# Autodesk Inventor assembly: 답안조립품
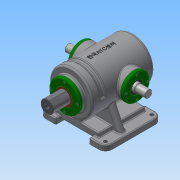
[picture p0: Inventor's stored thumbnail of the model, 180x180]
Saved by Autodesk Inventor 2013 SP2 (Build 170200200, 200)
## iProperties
Created: 2018-06
Part Number: 답안조립품
Document SubType Name: Assembly
Designer: Administrator
Mass: 8560.8 g
Surface Area: 4294.68 cm^2
Volume: 2307.11 cm^3
Density: 3.71062 g/cm^3
Author: Administrator
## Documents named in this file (13)
- C:\Users\Administrator\Desktop\380628V1011\답안조립품.iam
- C:\Users\Administrator\Desktop\380628V1011\본체.ipt
- C:\Users\Administrator\Desktop\380628V1011\가변스프링.ipt
- C:\Users\Administrator\Desktop\380628V1011\베어링 6205.ipt
- 베어링 6205.ipt
- C:\Users\Administrator\Desktop\380628V1011\볼트 M4.ipt
- C:\Users\Administrator\Desktop\380628V1011\부시.ipt
- C:\Users\Administrator\Desktop\380628V1011\슬라이드 커버.ipt
- C:\Users\Administrator\Desktop\380628V1011\슬라이드.ipt
- C:\Users\Administrator\Desktop\380628V1011\오일실.ipt
- 오일실.ipt
- C:\Users\Administrator\Desktop\380628V1011\축 커버.ipt
- C:\Users\Administrator\Desktop\380628V1011\편심축.ipt
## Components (1 placed, 1 different names)
1. 가변스프링:1
